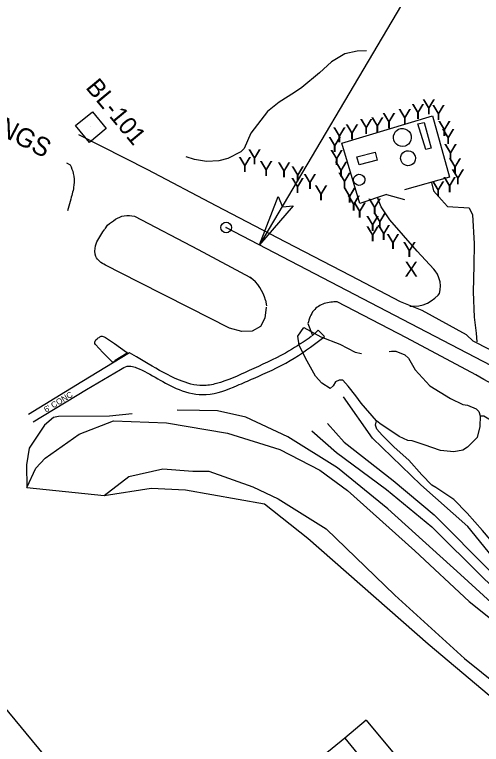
# Model space of a CAD drawing. Extents: x 2057130 to 2060012, y 687175 to 689912.
# Drawn here: x 2058184.2 to 2058494.6, y 688749 to 689234.1 of the extents above; entities that cross this region are included whole.
import ezdxf

# ---------------------------------------------------------------- set-up
doc = ezdxf.new("R2010")
doc.units = 0
for name, color, linetype in [('CTL Sheet Datum Description CELL', 7, 'Continuous'), ('CTL Sheet Table Cell', 7, 'Continuous'), ('CTL Supplemental Horizontal and Vertical CELL', 7, 'Continuous'), ('CTL Supplemental Horizontal and Vertical Text', 7, 'Continuous'), ('Exist Hydro Jurisdictional Stream or Body of Water', 7, 'Continuous'), ('Exist Other Culture Fence Line', 7, 'Continuous'), ('Exist Roads Curbs', 7, 'Continuous'), ('Exist Roads EOP', 7, 'Continuous'), ('Exist Roads EOP Other', 7, 'Continuous'), ('Exist Roads EOP Text', 7, 'Continuous'), ('Exist Roads Soil', 7, 'Continuous'), ('Old_Level_11', 7, 'Continuous'), ('Old_Level_8', 7, 'Continuous'), ('Old_Level_9', 7, 'Continuous'), ('Prop Horizontal Alignment', 7, 'Continuous'), ('Prop Horizontal Alignment Station Label', 7, 'Continuous'), ('Prop Terminator CELL', 7, 'Continuous')]:
    doc.layers.add(name, color=color, linetype=linetype)

msp = doc.modelspace()

# ---------------------------------------------------------------- linework, layer by layer
at = {"layer": 'CTL Sheet Table Cell'}
for p, q in [((2057937.41, 689063.15), (2058269.88, 688662.23)), ((2058418.1, 688765.11), (2058403.78, 688753.23)), ((2058418.1, 688765.11), (2058861.38, 688230.54)), ((2058403.78, 688753.23), (2058389.46, 688741.36)), ((2058403.78, 688753.23), (2058847.06, 688218.67))]:
    msp.add_line(p, q, dxfattribs=at)
at = {"layer": 'CTL Supplemental Horizontal and Vertical CELL'}
msp.add_line((2058234.99, 689159.42), (2058234.99, 689159.42), dxfattribs=at)
msp.add_lwpolyline([(2058235.99, 689169.56), (2058245.21, 689158.39), (2058234.02, 689149.16), (2058224.81, 689160.32)], close=True, dxfattribs=at)
at = {"layer": 'Exist Hydro Jurisdictional Stream or Body of Water'}
for points in [[(2058192.4, 688919.82), (2058198.27, 688932.61), (2058204.65, 688939.18), (2058227.07, 688955.32), (2058249.92, 688964.13), (2058285.27, 688962.84), (2058325.82, 688955.88), (2058360.5, 688944.99), (2058387.28, 688931.3), (2058405.58, 688917.9), (2058450.27, 688877.8), (2058486.44, 688844.08), (2058518.19, 688818.85), (2058538.85, 688801.67), (2058576.83, 688773.18), (2058623.58, 688752.3), (2058651.31, 688737.29)], [(2058243.89, 688914.56), (2058260.21, 688927.16), (2058282.83, 688932.24), (2058302.77, 688930.57), (2058313.28, 688930.57), (2058342.56, 688920.21), (2058359.45, 688912.16), (2058391.34, 688892.22), (2058437.08, 688848.29), (2058483.4, 688806.09), (2058518.34, 688778.04), (2058549.65, 688756.51), (2058569.58, 688744.33), (2058626.48, 688731.86), (2058638.93, 688727.61)]]:
    msp.add_lwpolyline(points, dxfattribs=at)
at = {"layer": 'Exist Other Culture Fence Line'}
for points in [[(2058401.91, 689148.75), (2058462.01, 689166.92), (2058473.51, 689125.98), (2058443.39, 689117.71)], [(2058431.44, 689114.46), (2058413.71, 689108.5), (2058401.91, 689148.75)]]:
    msp.add_lwpolyline(points, dxfattribs=at)
at = {"layer": 'Exist Roads Curbs'}
for p, q in [((2058242.95, 689009.49), (2058238.03, 689014.76)), ((2058248.18, 689004.14), (2058242.95, 689009.49)), ((2058259.15, 689009.16), (2058251.06, 689004.22))]:
    msp.add_line(p, q, dxfattribs=at)
msp.add_lwpolyline([(2058244.59, 689019.53), (2058250.58, 689015.59), (2058258.57, 689009.8), (2058259.15, 689009.16)], dxfattribs=at)
msp.add_arc((2058249.6, 689004.98), 1.65, 210.5822, 332.4379, dxfattribs=at)
msp.add_spline([(2058238.03, 689014.76), (2058237.49, 689016.32), (2058239.91, 689019.23), (2058241.79, 689020.34), (2058244.59, 689019.53)], degree=3, dxfattribs=at)
at = {"layer": 'Exist Roads EOP'}
for p, q in [((2058218.69, 689135.67), (2058221.24, 689134.27)), ((2058221.59, 689111.54), (2058219.36, 689103.68)), ((2058264, 689100.06), (2058306.22, 689078.02)), ((2058264, 689100.06), (2058306.22, 689078.02)), ((2058242.99, 689089.77), (2058244.2, 689091.54)), ((2058244.37, 689091.77), (2058245.94, 689094.13)), ((2058244.37, 689091.77), (2058245.94, 689094.13)), ((2058306.22, 689078.02), (2058340.72, 689059.49)), ((2058306.22, 689078.02), (2058340.72, 689059.49)), ((2058351.02, 689044.23), (2058351.65, 689040.44)), ((2058351.02, 689044.23), (2058351.65, 689040.44)), ((2058444.72, 689019.32), (2058398.79, 689043.29)), ((2058379.26, 689028.8), (2058382.08, 689021.43)), ((2058381.61, 689020.34), (2058380.05, 689019.04)), ((2058490.85, 688994.7), (2058444.72, 689019.32))]:
    msp.add_line(p, q, dxfattribs=at)
for points in [[(2058500.05, 689011.62), (2058489.26, 689017.05), (2058484.73, 689021.35), (2058455.29, 689037.52), (2058440.84, 689043.12), (2058407.76, 689060.49), (2058364.53, 689082.85), (2058318.19, 689106.92), (2058272.72, 689130.83), (2058226.89, 689154.25)], [(2058351.54, 689039.62), (2058350.53, 689032.39), (2058347.64, 689026.75), (2058342.25, 689023.67), (2058335.25, 689023.45), (2058327.06, 689025.73), (2058300.52, 689039.22), (2058266.95, 689056.18), (2058244.68, 689067.61)], [(2058273.09, 689001.9), (2058265.37, 689006.55), (2058260.68, 689009.29), (2058228.92, 688990.01), (2058193.4, 688968.41)]]:
    msp.add_lwpolyline(points, dxfattribs=at)
msp.add_arc((2058326.02, 689038.47), 25.65, 12.9773, 55.0366, dxfattribs=at)
msp.add_ellipse((2058326.06, 689038.46), major_axis=(-1.28, 25.61), ratio=0.998882, start_param=4.889126, end_param=5.623594, dxfattribs=at)
for points in [[(2058221.24, 689134.27), (2058223.27, 689128.59), (2058223.66, 689120.69), (2058221.59, 689111.54)], [(2058245.94, 689094.13), (2058251.35, 689098.06), (2058257.13, 689100.39), (2058264, 689100.06)], [(2058245.94, 689094.13), (2058251.35, 689098.06), (2058257.13, 689100.39), (2058264, 689100.06)], [(2058244.68, 689067.61), (2058240.62, 689070.18), (2058238.3, 689073.25), (2058238.13, 689080.51), (2058242.99, 689089.77)], [(2058398.79, 689043.29), (2058390.15, 689042.05), (2058383.11, 689037.39), (2058379.26, 689028.8)], [(2058380.05, 689019.04), (2058364.29, 689009.19), (2058340.2, 688997.49), (2058318.41, 688988.88), (2058309.39, 688987.51), (2058293.79, 688991.16), (2058273.09, 689001.9)], [(2058790.44, 688783.33), (2058774.52, 688799.91), (2058750.56, 688821.57), (2058724.88, 688843.53), (2058697.06, 688865.63), (2058669.08, 688886.89), (2058642.64, 688905.34), (2058608.82, 688927.02), (2058574.14, 688948.51), (2058534.92, 688970.39), (2058490.85, 688994.7)]]:
    msp.add_spline(points, degree=3, dxfattribs=at)
at = {"layer": 'Exist Roads EOP Other'}
for points in [[(2058461.38, 689122.49), (2058462.8, 689117.07), (2058468.11, 689110.92), (2058472, 689106.57), (2058486.4, 689105.69), (2058488.67, 689101.02), (2058489.72, 689082.06), (2058489.6, 689067.43), (2058489.1, 689049.77), (2058489.77, 689032.99), (2058491.07, 689022.32), (2058491.56, 689016.66)], [(2058447.02, 689040.43), (2058450.01, 689040.33), (2058452.98, 689040.62), (2058455.89, 689041.3), (2058458.69, 689042.36), (2058461.32, 689043.78), (2058463.74, 689045.53), (2058465.91, 689047.58), (2058466.83, 689048.64), (2058467.32, 689051.25), (2058467.41, 689053.9), (2058467.11, 689056.53), (2058466.42, 689059.09), (2058465.36, 689061.51), (2058463.95, 689063.76), (2058463.02, 689064.91), (2058451.89, 689076.93), (2058433.68, 689097.72), (2058428.01, 689106.4), (2058425.63, 689112.47)], [(2058388.89, 689018.98), (2058390.29, 689020.23), (2058386, 689024.38), (2058382.05, 689020.53)], [(2058196.59, 688963.42), (2058232.13, 688984.97), (2058254.7, 688998.23)]]:
    msp.add_lwpolyline(points, dxfattribs=at)
msp.add_spline([(2058254.7, 688998.23), (2058259.03, 689000.39), (2058261.61, 689000.49), (2058265.31, 688999.4), (2058293.55, 688984.91), (2058311.62, 688981.63), (2058332.29, 688987.58), (2058343.11, 688992.31), (2058367.43, 689004.12), (2058388.89, 689018.98)], degree=3, dxfattribs=at)
at = {"layer": 'Exist Roads Soil'}
for points in [[(2058392.23, 688962.26), (2058403.46, 688949.91), (2058436.05, 688924.4), (2058463.33, 688901.57), (2058501.42, 688863.21), (2058528.5, 688838.55), (2058566.54, 688802.58), (2058595.96, 688784), (2058631.65, 688776.32), (2058672.35, 688770.1)], [(2058381.8, 688957.42), (2058398.21, 688943), (2058431.63, 688918.41), (2058461.61, 688893.72), (2058495.76, 688859.78), (2058526.85, 688830.27), (2058560.88, 688799.23), (2058594.24, 688776.2), (2058631.79, 688769.37), (2058672.86, 688764.1)]]:
    msp.add_lwpolyline(points, dxfattribs=at)
at = {"layer": 'Old_Level_11'}
for points in [[(2058418.33, 689210.03), (2058412.06, 689209.77), (2058403.9, 689207.97), (2058394.95, 689202.65), (2058387.03, 689195.4), (2058375.19, 689185.57), (2058370.39, 689182.42), (2058360.15, 689175.93), (2058352.39, 689169.62), (2058341.28, 689155.23), (2058336.89, 689145.21), (2058334.75, 689142.91), (2058326.07, 689138.56), (2058319.95, 689136.9), (2058311.9, 689136.54), (2058303.94, 689137.79), (2058298.21, 689139.52)], [(2058433.2, 689010.08), (2058434.81, 689010.4), (2058437.73, 689010.34), (2058443.73, 689007.89), (2058446.23, 689005.74), (2058450.63, 688998.05), (2058460.3, 688987.45), (2058474.02, 688978.94), (2058482.27, 688975.07), (2058485.36, 688974.59), (2058491.06, 688972.06), (2058492.87, 688970.25), (2058493.72, 688967.38), (2058493.53, 688960.34), (2058491.81, 688953.08), (2058485.3, 688946.5), (2058482.27, 688944.55), (2058476.28, 688943.58), (2058467.37, 688944.38), (2058456.51, 688948.2), (2058448.5, 688950.77), (2058445.8, 688951.02), (2058439.91, 688953.76), (2058427.11, 688962.32), (2058424.79, 688964.06), (2058414.68, 688975.8), (2058411.13, 688980.83), (2058406.05, 688987.15), (2058402.45, 688991.18), (2058399.94, 688991.22), (2058397.65, 688989.94), (2058396.1, 688987.41), (2058394.09, 688985.6), (2058388.45, 688989.14), (2058384.28, 688993.8), (2058377.59, 689005.73), (2058373.55, 689014.5), (2058372.58, 689020.49), (2058376.63, 689026.22)], [(2058376.63, 689026.22), (2058387.95, 689019.95), (2058400.47, 689015.14), (2058410.63, 689009.74), (2058414.82, 689008.84)], [(2058493.72, 688967.38), (2058496.23, 688967.34), (2058500.72, 688964.67), (2058505.57, 688961.38), (2058513.88, 688959.09), (2058515.82, 688956.29)], [(2058532.81, 688849.75), (2058531, 688851.57), (2058528.26, 688852.55), (2058521.3, 688857.59), (2058516.39, 688861.6), (2058512.82, 688866.23), (2058509.12, 688872.08), (2058504.26, 688880.72), (2058495.27, 688891.2), (2058485.13, 688902.75), (2058476.37, 688911.9), (2058464.41, 688919.73), (2058461.58, 688921.4), (2058455.02, 688928.31), (2058446.29, 688938.07), (2058436.58, 688946.55), (2058428.75, 688954.61), (2058425.15, 688958.63), (2058424.1, 688961.31), (2058424.79, 688964.06)]]:
    msp.add_lwpolyline(points, dxfattribs=at)
at = {"layer": 'Old_Level_8'}
for p, q in [((2058431.44, 689114.46), (2058443.42, 689111.3)), ((2058192.4, 688919.82), (2058243.89, 688914.56))]:
    msp.add_line(p, q, dxfattribs=at)
for points in [[(2058457.6, 689144.36), (2058452.43, 689161.41), (2058456.5, 689162.39), (2058461.27, 689145.35), (2058457.6, 689144.36)], [(2058443.83, 689146.76), (2058442.32, 689146.51), (2058440.8, 689146.65), (2058439.36, 689147.17), (2058438.1, 689148.04), (2058437.11, 689149.21), (2058436.44, 689150.59), (2058436.15, 689152.09), (2058436.25, 689153.62), (2058436.74, 689155.07), (2058437.58, 689156.35), (2058438.71, 689157.37), (2058439.61, 689157.88), (2058441.07, 689158.33), (2058442.6, 689158.38), (2058444.1, 689158.05), (2058445.45, 689157.34), (2058446.59, 689156.32), (2058447.42, 689155.04), (2058447.91, 689153.58), (2058448, 689152.06), (2058447.71, 689150.56), (2058447.04, 689149.18), (2058446.05, 689148.02), (2058444.79, 689147.15), (2058443.83, 689146.76)], [(2058425.41, 689137.38), (2058413.41, 689134.25), (2058411.81, 689139.65), (2058424.02, 689142.78), (2058425.41, 689137.38)], [(2058441.18, 689137.13), (2058440.91, 689138.49), (2058441.05, 689139.87), (2058441.56, 689141.16), (2058442.41, 689142.26), (2058443.54, 689143.07), (2058444.84, 689143.53), (2058446.23, 689143.61), (2058447.58, 689143.3), (2058448.79, 689142.63), (2058449.77, 689141.64), (2058450.43, 689140.42), (2058450.52, 689140.14), (2058450.77, 689138.77), (2058450.63, 689137.39), (2058450.11, 689136.1), (2058449.26, 689135.02), (2058448.13, 689134.21), (2058446.82, 689133.75), (2058445.43, 689133.68), (2058444.08, 689134), (2058442.87, 689134.68), (2058441.9, 689135.67), (2058441.25, 689136.9), (2058441.18, 689137.13)], [(2058417.05, 689125.39), (2058417.18, 689124.17), (2058416.92, 689122.98), (2058416.29, 689121.93), (2058415.37, 689121.13), (2058414.24, 689120.67), (2058413.02, 689120.58), (2058411.84, 689120.89), (2058410.81, 689121.55), (2058410.05, 689122.51), (2058409.63, 689123.65), (2058409.62, 689123.69), (2058409.65, 689124.92), (2058410.07, 689126.07), (2058410.83, 689127.02), (2058411.86, 689127.69), (2058413.04, 689128.01), (2058414.26, 689127.93), (2058415.4, 689127.47), (2058416.33, 689126.68), (2058416.96, 689125.63), (2058417.05, 689125.39)], [(2058710.76, 688777.94), (2058639.82, 688785.6), (2058579.89, 688802.35), (2058544.82, 688828.11), (2058510.55, 688863.02), (2058485.54, 688893.98), (2058454.38, 688921.53), (2058422.23, 688952.56), (2058403.03, 688979.97)], [(2058734.92, 688753.52), (2058735.51, 688760.64), (2058736.99, 688765.98), (2058740.85, 688771.33), (2058730.47, 688774.89), (2058710.76, 688777.94), (2058683.64, 688756.81), (2058647.8, 688760.5), (2058609.04, 688770.73), (2058573.94, 688781.35), (2058554.73, 688796.64), (2058518.83, 688827.17), (2058480.84, 688861.92), (2058432.5, 688905.71), (2058398.97, 688932.94), (2058365.98, 688953.37), (2058338.05, 688966.46), (2058319.19, 688970.72), (2058307.26, 688971.08), (2058292.32, 688971.2)], [(2058262.4, 688968.84), (2058247.4, 688967.16), (2058213.49, 688967.02), (2058210.14, 688966.31), (2058204.14, 688961.13), (2058193.89, 688945.9), (2058192.18, 688934.88), (2058192.4, 688919.82)], [(2058243.89, 688914.56), (2058274.94, 688919.33), (2058297.8, 688918.3), (2058350.46, 688908.85), (2058379.27, 688886.03), (2058459.18, 688815.88), (2058518.04, 688766.49), (2058546.6, 688746.07), (2058577.46, 688734.39), (2058606.33, 688729.69), (2058618.83, 688725.97), (2058623.23, 688723.41), (2058623.36, 688718.56), (2058621.09, 688706.79), (2058622.32, 688699.87), (2058624.31, 688695.72), (2058627.84, 688693.91), (2058629.3, 688692.92), (2058633.15, 688691.6), (2058635.7, 688693.01)]]:
    msp.add_lwpolyline(points, dxfattribs=at)
at = {"layer": 'Prop Horizontal Alignment'}
msp.add_line((2058324.9, 689092.58), (2058553.22, 688973.76), dxfattribs=at)
for radius in [3.55, 0.114]:
    msp.add_circle((2058324.9, 689092.58), radius, dxfattribs=at)
at = {"layer": 'Prop Horizontal Alignment Station Label'}
msp.add_line((2058456.09, 689265.51), (2058347.08, 689081.04), dxfattribs=at)
at = {"layer": 'Prop Terminator CELL'}
msp.add_lwpolyline([(2058369.42, 689107), (2058347.09, 689081.03), (2058359.38, 689113.23), (2058362.31, 689106.44)], close=True, dxfattribs=at)

# ---------------------------------------------------------------- texts
at = {"layer": 'CTL Sheet Datum Description CELL'}
for s, p in [('ALL LINEAR DIMENSIONS ARE LOCALIZED HORIZONTAL DISTANCES', (2058429.24, 689474.05)), ('VERTICAL DATUM USED IS NAVD 88', (2058479.59, 689384.58))]:
    msp.add_text(s, height=10.4266, rotation=309.6672, dxfattribs=at).set_placement(p)
at = {"layer": 'CTL Supplemental Horizontal and Vertical Text'}
msp.add_text('BL-101', height=11.79, rotation=309.6672, dxfattribs=at).set_placement((2058231.02, 689185.47))
at = {"layer": 'Exist Roads EOP Text'}
msp.add_text("6' CONC", height=4, rotation=31.3169, dxfattribs=at).set_placement((2058205.24, 688969.42))
at = {"layer": 'Old_Level_11'}
for s, p in [('Y', (2058447.97, 689164.79)), ('Y', (2058455.19, 689167.81)), ('Y', (2058461.62, 689164.03)), ('Y', (2058439.22, 689161.35)), ('Y', (2058413.58, 689154.82)), ('Y', (2058420.99, 689155.92)), ('Y', (2058428.69, 689158.61)), ('Y', (2058404.11, 689151.12)), ('Y', (2058465.56, 689153.43)), ('Y', (2058395.75, 689149.17)), ('Y', (2058468.08, 689148.06)), ('Y', (2058392.67, 689142.8)), ('Y', (2058469.63, 689138)), ('Y', (2058339.32, 689134.52)), ('Y', (2058393.89, 689134.16)), ('Y', (2058332.9, 689129.55)), ('Y', (2058347.04, 689126.74)), ('Y', (2058358.96, 689125.96)), ('Y', (2058396.87, 689126.35)), ('Y', (2058472.64, 689128.67)), ('Y', (2058368.06, 689123.23)), ('Y', (2058474.54, 689121.21)), ('Y', (2058367.93, 689115.49)), ('Y', (2058376.14, 689118.25)), ('Y', (2058399.18, 689119.08)), ('Y', (2058469.01, 689116.08)), ('Y', (2058383.55, 689110.59)), ('Y', (2058461.41, 689113.35)), ('Y', (2058402.55, 689109.15)), ('Y', (2058405.28, 689103.78)), ('Y', (2058419.16, 689101.69)), ('Y', (2058409.26, 689099.15)), ('Y', (2058422.63, 689092.25)), ('Y', (2058417.83, 689090.22)), ('Y', (2058417.85, 689083.38)), ('Y', (2058425.25, 689084.27)), ('Y', (2058431.36, 689078.29)), ('Y', (2058442.31, 689072.93)), ('X', (2058443.5, 689059.87))]:
    msp.add_text(s, height=10, dxfattribs=at).set_placement(p)
at = {"layer": 'Old_Level_9'}
msp.add_text('TO HOLLY SPRINGS', height=12.5, rotation=332.2356, dxfattribs=at).set_placement((2058060.33, 689214.28))

doc.saveas('drawing.dxf')
